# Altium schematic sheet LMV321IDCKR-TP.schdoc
size 127 x 101 mm
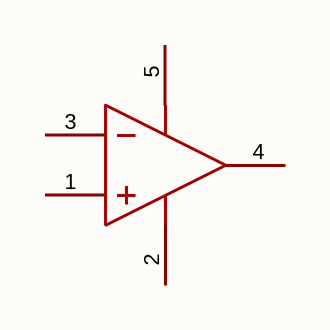
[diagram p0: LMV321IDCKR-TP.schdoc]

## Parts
U?  lmv321idckr-tp  [SOT-353-5_L2.1-W1.3-P0.65-LS2.3-BL]  (value not drawn)

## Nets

Not connected (* = marked no-connect by the designer): U? 1(IN+) 2(V-) 3(IN-) 4(OUT) 5(V+)

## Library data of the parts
U? = lmv321idckr-tp: Manufacturer: TECH PUBLIC(台舟); AddInBom: yes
